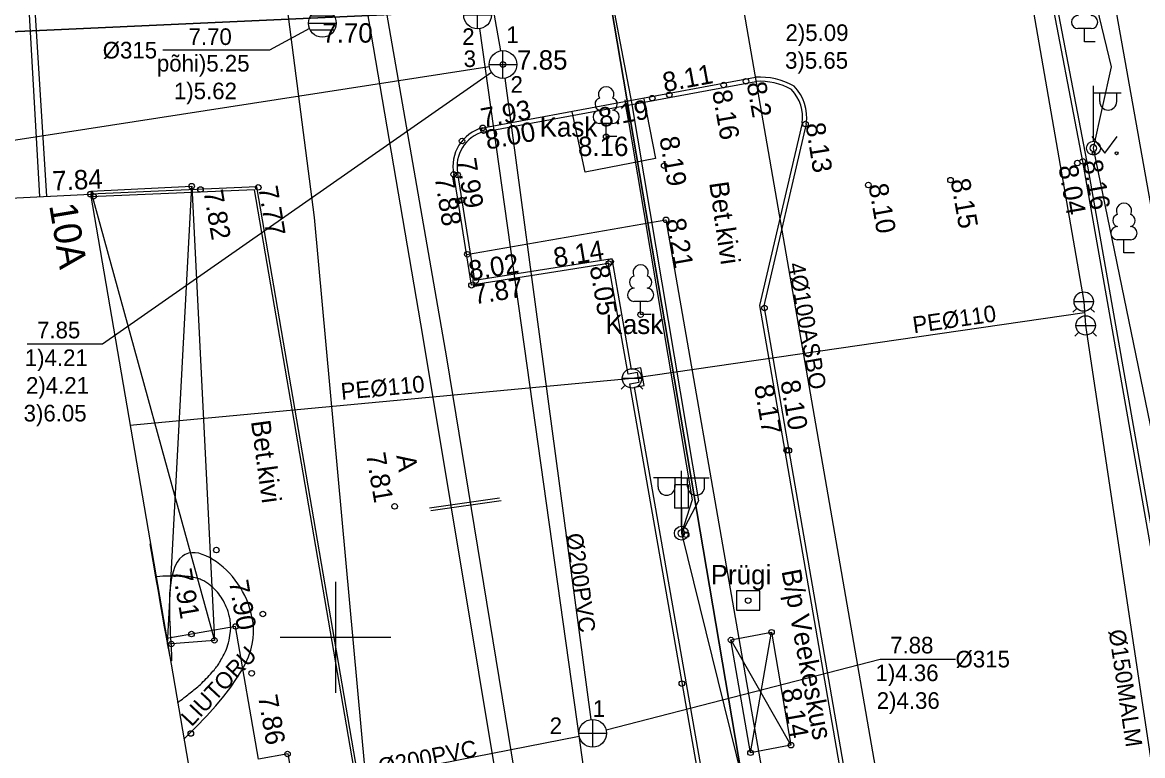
# Model space of a CAD drawing. Extents: x 473307 to 473719, y 6532843 to 6533381.
# Drawn here: x 473588.69 to 473629.14, y 6533195.73 to 6533222.19 of the extents above; entities that cross this region are included whole.
import ezdxf

# ---------------------------------------------------------------- set-up
doc = ezdxf.new("R2010")
doc.units = 0
for name, color, linetype in [('Default', 7, 'Continuous'), ('HALJASTUS', 7, 'Continuous'), ('HOONE', 7, 'Continuous'), ('HOONEDET', 7, 'Continuous'), ('KKAEV', 7, 'Continuous'), ('KKAEV_NR', 7, 'Continuous'), ('KORGUS', 7, 'Continuous'), ('KPKAABEL', 7, 'Continuous'), ('KTRASS', 7, 'Continuous'), ('KTRASS_TEKST', 7, 'Continuous'), ('LIIKLUS', 7, 'Continuous'), ('MPKAABEL', 7, 'Continuous'), ('PIIR', 7, 'Continuous'), ('POST', 7, 'Continuous'), ('PUU', 7, 'Continuous'), ('RAJATIS', 7, 'Continuous'), ('RAJATISEDET', 7, 'Continuous'), ('SITRASS', 7, 'Continuous'), ('SITRASS_TEKST', 7, 'Continuous'), ('SKKAEV', 7, 'Continuous'), ('SKKAEV_NR', 7, 'Continuous'), ('SKTRASS', 7, 'Continuous'), ('TEE', 7, 'Continuous'), ('TTRASS', 7, 'Continuous'), ('VKAEV', 7, 'Continuous'), ('VORK', 7, 'Continuous'), ('VTRASS', 7, 'Continuous'), ('VTRASS_TEKST', 7, 'Continuous')]:
    doc.layers.add(name, color=color, linetype=linetype)

# ---------------------------------------------------------------- blocks, each defined once
blk = doc.blocks.new('LEHTP1')
at = {"layer": 'Default'}
for p, q in [((0.48, 0.95), (-0.48, 0.95)), ((0, 0), (0, 0.95)), ((0.76, 0), (0, 0))]:
    blk.add_line(p, q, dxfattribs=at)
for centre, radius, start, end in [((0, 3.04), 0.554, 332.5799, 207.4201), ((-0.34, 2.345), 0.465, 109.02174, 253.14154), ((0.34, 2.345), 0.465, 286.85082, 70.98591), ((-0.475, 1.425), 0.475, 90.0016, 269.3953), ((0.475, 1.425), 0.475, 270.6047, 89.9984)]:
    blk.add_arc(centre, radius, start, end, dxfattribs=at)
blk = doc.blocks.new('KAKAEV')
at = {"layer": 'Default'}
for p, q in [((0, -1), (0, 1)), ((-1, 0), (1, 0))]:
    blk.add_line(p, q, dxfattribs=at)
blk.add_circle((0, 0), 1, dxfattribs=at)
blk = doc.blocks.new('REKAEV')
at = {"layer": 'Default'}
for p, q in [((-1, 0), (1, 0)), ((0.86, 0.5), (-0.86, 0.5)), ((0.86, -0.5), (-0.86, -0.5))]:
    blk.add_line(p, q, dxfattribs=at)
blk.add_circle((0, 0), 1, dxfattribs=at)
blk = doc.blocks.new('VESIIB')
at = {"layer": 'Default'}
for p, q in [((-0.7, 0), (0.7, 0)), ((-0.495, -0.495), (-0.774, -0.774)), ((0.495, -0.495), (0.774, -0.774))]:
    blk.add_line(p, q, dxfattribs=at)
blk.add_circle((0, 0), 0.7, dxfattribs=at)
blk = doc.blocks.new('MEPOST')
at = {"layer": 'Default'}
blk.add_circle((0, 0), 0.5, dxfattribs=at)
for start, end in [(0, 180), (180, 0)]:
    blk.add_arc((0, 0), 0.25, start, end, dxfattribs=at)
blk = doc.blocks.new('VAPOS2')
at = {"layer": 'Default'}
for p, q in [((0, 0.5), (0, 4.5)), ((0, 4), (-2, 4)), ((-1.679, 3.358), (-1.679, 4)), ((-0.453, 3.358), (-0.453, 4)), ((0, 4), (2, 4)), ((0.453, 3.358), (0.453, 4)), ((1.679, 3.358), (1.679, 4))]:
    blk.add_line(p, q, dxfattribs=at)
for centre in [(-1.066, 3.358), (1.066, 3.358)]:
    blk.add_arc(centre, 0.613, 180, 0, dxfattribs=at)
blk = doc.blocks.new('MURU')
at = {"layer": 'Default'}
for p, q in [((-0.927, 1.213), (0, 0)), ((0, 0), (0.891, 1.213))]:
    blk.add_line(p, q, dxfattribs=at)
for centre in [(-0.802, 0), (0.856, 0)]:
    blk.add_circle(centre, 0.11, dxfattribs=at)
blk = doc.blocks.new('VAPOST')
at = {"layer": 'Default'}
for p, q in [((0, 0.5), (0, 4.5)), ((0, 4), (2, 4)), ((0.453, 3.358), (0.453, 4)), ((1.679, 3.358), (1.679, 4))]:
    blk.add_line(p, q, dxfattribs=at)
blk.add_arc((1.066, 3.358), 0.613, 180, 0, dxfattribs=at)
blk = doc.blocks.new('LIIKLM')
at = {"layer": 'Default'}
for points in [[(-0.5, 3.5), (-0.5, 1.8)], [(0.5, 3.5), (-0.5, 3.5)], [(0.5, 3.5), (0.5, 1.8)], [(0.5, 1.8), (-0.5, 1.8)], [(0, 1.8), (0, 0)], [(0.5, 0), (0, 0)]]:
    blk.add_lwpolyline(points, dxfattribs=at)
blk = doc.blocks.new('VKORIS')
at = {"layer": 'Default'}
for p, q in [((0, 4), (0, -4)), ((-4, 0), (4, 0))]:
    blk.add_line(p, q, dxfattribs=at)
blk = doc.blocks.new('rajatm')
at = {"layer": 'Default'}
blk.add_lwpolyline([(0.843, 0.702), (-0.843, 0.702), (-0.843, -0.702), (0.843, -0.702)], close=True, dxfattribs=at)

msp = doc.modelspace()

# ---------------------------------------------------------------- linework, layer by layer
at = {"layer": 'HOONE'}
msp.add_lwpolyline([(473567.695, 6533214.825), (473591.147, 6533215.988), (473597.944, 6533176.46), (473598.021, 6533176.467), (473599.163, 6533169.838), (473569.973, 6533168.376), (473567.695, 6533214.825)], dxfattribs=at)
at = {"layer": 'HOONEDET'}
for p, q in [((473591.16, 6533216.1), (473595.626, 6533199.888)), ((473593.933, 6533199.746), (473594.814, 6533216.278))]:
    msp.add_line(p, q, dxfattribs=at)
msp.add_lwpolyline([(473591.16, 6533216.1), (473594.814, 6533216.278), (473595.626, 6533199.888), (473593.933, 6533199.746)], dxfattribs=at)
at = {"layer": 'KKAEV_NR'}
for points in [[(473605.633, 6533220.382), (473591.582, 6533210.582), (473588.861, 6533210.582)], [(473609.769, 6533196.66), (473619.666, 6533199.211), (473622.387, 6533199.211)]]:
    msp.add_lwpolyline(points, dxfattribs=at)
at = {"layer": 'KORGUS'}
for centre in [(473606.043, 6533220.668), (473614.016, 6533219.929), (473614.819, 6533220.064), (473612.051, 6533219.573), (473611.435, 6533219.453), (473605.315, 6533218.384), (473616.967, 6533218.52), (473604.567, 6533217.909), (473605.347, 6533218.284), (473609.771, 6533218.065), (473626.786, 6533217.111), (473626.98, 6533217.172), (473604.267, 6533216.706), (473604.409, 6533216.685), (473611.865, 6533217.019), (473594.804, 6533216.277), (473619.239, 6533216.318), (473622.205, 6533216.497), (473591.147, 6533215.988), (473591.262, 6533215.91), (473595.124, 6533216.16), (473597.208, 6533216.233), (473604.438, 6533215.747), (473604.56, 6533215.775), (473611.931, 6533215.063), (473604.758, 6533213.821), (473609.86, 6533213.484), (473609.933, 6533213.555), (473604.907, 6533212.703), (473605.063, 6533212.869), (473615.489, 6533211.883), (473611.016, 6533211.643), (473616.289, 6533206.748), (473616.365, 6533206.742), (473602.132, 6533204.723), (473612.658, 6533203.699), (473595.696, 6533203.145), (473614.897, 6533201.323), (473597.373, 6533200.84), (473594.8, 6533200.115), (473596.392, 6533200.39), (473615.743, 6533200.181), (473594.071, 6533199.757), (473595.626, 6533199.888), (473614.278, 6533199.901), (473596.971, 6533198.7), (473612.505, 6533198.328), (473594.776, 6533196.526), (473616.443, 6533196.104), (473598.267, 6533195.788), (473614.982, 6533195.832)]:
    msp.add_circle(centre, 0.1, dxfattribs=at)
at = {"layer": 'KPKAABEL'}
msp.add_lwpolyline([(473603.611, 6533167.485), (473599.245, 6533215.151), (473598.214, 6533223.062)], dxfattribs=at)
at = {"layer": 'KTRASS'}
for points in [[(473596.379, 6533274.552), (473599.595, 6533256.427), (473604.261, 6533230.713), (473605.956, 6533221.161)], [(473577.339, 6533216.231), (473605.549, 6533220.592)], [(473606.109, 6533220.173), (473609.219, 6533197.031)], [(473594.926, 6533193.714), (473608.797, 6533196.428)]]:
    msp.add_lwpolyline(points, dxfattribs=at)
at = {"layer": 'MPKAABEL'}
for points in [[(473636.059, 6533169.782), (473634.239, 6533181.673), (473632.606, 6533189.833), (473631.267, 6533197.327), (473629.932, 6533205.197), (473627.365, 6533217.651), (473628.02, 6533220.588), (473626.187, 6533228.162), (473625.63, 6533235.006), (473624.395, 6533236.238), (473625.088, 6533237.039), (473624.62, 6533240.685), (473623.001, 6533248.826), (473621.554, 6533256.337), (473620.191, 6533259.447), (473620.669, 6533261.927), (473620.008, 6533272.193), (473619.024, 6533281.587), (473618.831, 6533288.933), (473618.813, 6533289.306)], [(473627.365, 6533217.651), (473628.02, 6533220.588), (473626.187, 6533228.162), (473625.63, 6533235.006), (473624.395, 6533236.238)], [(473607.954, 6533230.431), (473608.769, 6533229.316), (473610.682, 6533219.295), (473613.1, 6533204.928), (473612.486, 6533203.753)], [(473608.769, 6533229.316), (473610.682, 6533219.295), (473613.1, 6533204.928), (473612.486, 6533203.753), (473615.782, 6533190.445), (473617.366, 6533178.496)], [(473610.448, 6533219.399), (473610.475, 6533219.258), (473612.881, 6533204.963), (473612.486, 6533203.753)], [(473634.239, 6533181.673), (473632.606, 6533189.833), (473631.267, 6533197.327), (473629.932, 6533205.197), (473627.365, 6533217.651)], [(473603.39, 6533204.676), (473605.925, 6533205.032)], [(473603.44, 6533204.573), (473605.975, 6533204.929)], [(473612.486, 6533203.753), (473615.782, 6533190.445), (473617.366, 6533178.496), (473617.205, 6533177.267)]]:
    msp.add_lwpolyline(points, dxfattribs=at)
at = {"layer": 'PIIR'}
msp.add_lwpolyline([(473678.608, 6532842.593), (473677.66, 6532847.73), (473668.24, 6532906.4), (473664.64, 6532927.81), (473654.16, 6532926.37), (473630.89, 6533065.72), (473641.36, 6533067.51), (473636.3, 6533097.55), (473618.8, 6533170.64), (473609.94, 6533222.84), (473601.54, 6533272.81), (473599.09, 6533295.91), (473592.3, 6533328.43), (473587.14, 6533353.72), (473584.47, 6533353.28), (473580.56, 6533374.06), (473585.23, 6533374.14), (473584.699, 6533380.885)], dxfattribs=at)
for points in [[(473586.5, 6533271.93), (473601.56, 6533272.81), (473609.94, 6533222.84), (473586.39, 6533221.76), (473567.96, 6533221.17), (473565.61, 6533263.9), (473587.68, 6533264.9)], [(473558.63, 6533220.73), (473567.96, 6533221.17), (473586.39, 6533221.76), (473609.94, 6533222.84), (473618.8, 6533170.64), (473601.75, 6533167.04), (473561.43, 6533165.2), (473559.2, 6533209.37)]]:
    msp.add_lwpolyline(points, close=True, dxfattribs=at)
at = {"layer": 'RAJATIS'}
msp.add_lwpolyline([(473614.278, 6533199.901), (473615.743, 6533200.181), (473616.443, 6533196.104), (473614.982, 6533195.832), (473614.278, 6533199.901)], dxfattribs=at)
for points in [[(473594.523, 6533196.32), (473596.971, 6533198.7), (473597.373, 6533200.84), (473595.696, 6533203.145), (473593.308, 6533203.375), (473594.523, 6533196.32), (473593.308, 6533203.375)], [(473594.295, 6533197.641), (473594.359, 6533197.689), (473594.418, 6533197.733), (473594.807, 6533198.026), (473595.146, 6533198.31), (473595.626, 6533198.82), (473595.793, 6533199.044), (473596.048, 6533199.517), (473596.14, 6533199.778), (473596.209, 6533200.188), (473596.217, 6533200.34), (473596.2, 6533200.602), (473596.181, 6533200.712), (473596.118, 6533200.944), (473596.073, 6533201.062), (473595.906, 6533201.406), (473595.749, 6533201.62), (473595.495, 6533201.863), (473595.408, 6533201.931), (473595.225, 6533202.046), (473595.137, 6533202.086), (473594.915, 6533202.154), (473594.783, 6533202.179), (473594.476, 6533202.21), (473594.3, 6533202.215), (473593.923, 6533202.209), (473593.724, 6533202.198), (473593.512, 6533202.185)]]:
    msp.add_open_spline(points, degree=3, dxfattribs=at)
at = {"layer": 'RAJATISEDET'}
for points in [[(473614.278, 6533199.901), (473616.443, 6533196.104)], [(473614.982, 6533195.832), (473615.743, 6533200.181)]]:
    msp.add_lwpolyline(points, dxfattribs=at)
at = {"layer": 'SITRASS'}
msp.add_lwpolyline([(473619.598, 6533194.755), (473606.651, 6533269.171)], dxfattribs=at)
at = {"layer": 'SKKAEV_NR'}
msp.add_lwpolyline([(473599.056, 6533221.966), (473597.62, 6533221.186), (473593.765, 6533221.186)], dxfattribs=at)
at = {"layer": 'SKTRASS'}
msp.add_line((473605.197, 6533221.962), (473611.461, 6533177.365), dxfattribs=at)
at = {"layer": 'TEE'}
for points in [[(473633.632, 6533192.148), (473626.508, 6533232.017), (473625.67, 6533237.189), (473623.189, 6533236.957)], [(473631.487, 6533191.503), (473631.245, 6533193.006), (473626.98, 6533217.172), (473623.189, 6533236.957)], [(473631.635, 6533191.527), (473631.393, 6533193.031), (473627.128, 6533217.199), (473623.336, 6533236.985)], [(473605.315, 6533218.384), (473615.163, 6533220.21)], [(473605.348, 6533218.238), (473615.181, 6533220.061)], [(473611.137, 6533219.428), (473611.553, 6533217.274), (473609.014, 6533216.78), (473608.54, 6533218.956)], [(473616.846, 6533218.552), (473615.311, 6533211.969), (473616.217, 6533206.716), (473618.71, 6533192.337), (473619.951, 6533185.079), (473623.699, 6533179.197)], [(473616.994, 6533218.524), (473615.464, 6533211.964), (473616.365, 6533206.742), (473618.858, 6533192.362), (473620.094, 6533185.134), (473623.834, 6533179.264)], [(473610.621, 6533209.151), (473610.966, 6533209.211), (473610.906, 6533209.55), (473610.562, 6533209.489), (473609.86, 6533213.484), (473604.907, 6533212.703), (473604.267, 6533216.706)], [(473610.795, 6533209.029), (473611.14, 6533209.089), (473611.028, 6533209.723), (473610.683, 6533209.663), (473609.982, 6533213.655), (473605.032, 6533212.874), (473604.415, 6533216.733)], [(473600.715, 6533167.193), (473596.954, 6533189.064), (473601.687, 6533189.906), (473597.156, 6533216.255), (473591.147, 6533215.988)], [(473600.616, 6533167.176), (473596.838, 6533189.145), (473601.572, 6533189.987), (473597.073, 6533216.151), (473591.151, 6533215.888)], [(473604.729, 6533213.816), (473611.931, 6533215.063), (473614.566, 6533199.957), (473614.566, 6533199.957), (473615.517, 6533194.507), (473615.909, 6533192.334), (473618.695, 6533176.327)], [(473622.771, 6533177.029), (473616.417, 6533175.935), (473613.178, 6533194.593), (473610.621, 6533209.151)], [(473622.737, 6533177.176), (473616.539, 6533176.108), (473613.326, 6533194.619), (473610.795, 6533209.029)], [(473599.377, 6533189.495), (473598.294, 6533195.792), (473597.214, 6533195.606), (473596.392, 6533200.39), (473593.903, 6533199.96)]]:
    msp.add_lwpolyline(points, dxfattribs=at)
for centre, radius, start, end in [((473615.308, 6533217.701), 2.513, 60.2748, 93.297), ((473615.308, 6533217.701), 2.363, 60.7832, 93.0715), ((473615.416, 6533218.765), 1.446, 351.5554, 43.6997), ((473615.416, 6533218.765), 1.596, 351.3297, 44.5155), ((473605.673, 6533216.994), 1.436, 104.446, 191.5793), ((473605.673, 6533216.994), 1.286, 104.6697, 191.7208)]:
    msp.add_arc(centre, radius, start, end, dxfattribs=at)
at = {"layer": 'TTRASS'}
for points in [[(473592.297, 6533277.757), (473596.188, 6533254.087), (473601.84, 6533222.521), (473604, 6533210.082), (473607.02, 6533191.72), (473607.264, 6533190.194), (473603.552, 6533189.561), (473604.136, 6533186.261), (473607.868, 6533186.888), (473612.623, 6533162.34), (473616.873, 6533138.735), (473619.773, 6533121.514), (473620.151, 6533119.324)], [(473591.775, 6533277.426), (473595.59, 6533253.766), (473601.028, 6533223.219), (473603.147, 6533210.812), (473606.172, 6533192.662), (473606.51, 6533190.705), (473602.77, 6533190.028), (473603.588, 6533185.543), (473607.3, 6533186.208), (473612.067, 6533161.644), (473616.282, 6533137.983), (473619.426, 6533120.252), (473619.546, 6533119.497)], [(473589.32, 6533215.907), (473588.935, 6533222.692)], [(473589.576, 6533215.918), (473589.166, 6533222.448)]]:
    msp.add_lwpolyline(points, dxfattribs=at)
at = {"layer": 'VTRASS'}
for points in [[(473610.467, 6533298.54), (473612.816, 6533284.928), (473621.946, 6533241.242), (473627.014, 6533212.114), (473627.084, 6533211.254), (473634.761, 6533160.18), (473647.035, 6533084.422), (473650.297, 6533065.838)], [(473592.57, 6533207.655), (473610.704, 6533209.344), (473627.041, 6533211.717)]]:
    msp.add_lwpolyline(points, dxfattribs=at)

# ---------------------------------------------------------------- block references
at = {"layer": 'HALJASTUS', "xscale": 0.5, "yscale": 0.5}
msp.add_blockref('MURU', (473627.771, 6533217.467), dxfattribs=at)
at = {"layer": 'KKAEV', "xscale": 0.5, "yscale": 0.5}
for p in [(473606.043, 6533220.668), (473609.285, 6533196.536)]:
    msp.add_blockref('KAKAEV', p, dxfattribs=at)
at = {"layer": 'LIIKLUS', "xscale": 0.5, "yscale": 0.5}
msp.add_blockref('LIIKLM', (473612.486, 6533203.753), dxfattribs=at)
at = {"layer": 'POST', "xscale": 0.5, "yscale": 0.5}
for name, p in [('VAPOST', (473627.365, 6533217.651)), ('MEPOST', (473627.365, 6533217.651)), ('VAPOS2', (473612.486, 6533203.753)), ('MEPOST', (473612.486, 6533203.753))]:
    msp.add_blockref(name, p, dxfattribs=at)
at = {"layer": 'PUU', "xscale": 0.5, "yscale": 0.5}
for p in [(473627.047, 6533221.487), (473609.771, 6533218.065), (473628.467, 6533213.868), (473611.016, 6533211.643)]:
    msp.add_blockref('LEHTP1', p, dxfattribs=at)
at = {"layer": 'RAJATIS', "xscale": 0.5, "yscale": 0.5}
msp.add_blockref('rajatm', (473614.897, 6533201.323), dxfattribs=at)
at = {"layer": 'SKKAEV', "xscale": 0.5, "yscale": 0.5}
for name, p in [('KAKAEV', (473605.127, 6533222.457)), ('REKAEV', (473599.522, 6533222.157))]:
    msp.add_blockref(name, p, dxfattribs=at)
at = {"layer": 'VKAEV', "xscale": 0.5, "yscale": 0.5}
for p in [(473627.014, 6533212.114), (473627.084, 6533211.254), (473610.704, 6533209.344)]:
    msp.add_blockref('VESIIB', p, dxfattribs=at)
at = {"layer": 'VORK', "xscale": 0.5, "yscale": 0.5}
msp.add_blockref('VKORIS', (473600, 6533200), dxfattribs=at)

# ---------------------------------------------------------------- texts
at = {"layer": 'HOONE'}
msp.add_text('10A', height=1, rotation=279.457, dxfattribs=at).set_placement((473589.657, 6533215.591))
at = {"layer": 'KKAEV_NR'}
for s, p in [('1', (473606.167, 6533221.445)), ('3', (473604.625, 6533220.577)), ('2', (473606.318, 6533219.648)), ('7.85', (473589.222, 6533210.787)), ('1)4.21', (473588.779, 6533209.787)), ('2)4.21', (473588.822, 6533208.787)), ('3)6.05', (473588.736, 6533207.787)), ('7.88', (473620.026, 6533199.416)), ('%%c315', (473622.387, 6533198.911)), ('1)4.36', (473619.498, 6533198.416)), ('2)4.36', (473619.54, 6533197.416)), ('1', (473609.288, 6533197.128)), ('2', (473607.73, 6533196.506))]:
    msp.add_text(s, height=0.6, dxfattribs=at).set_placement(p)
at = {"layer": 'KORGUS'}
for s, p in [('7.70', (473599.522, 6533221.457)), ('7.85', (473606.553, 6533220.484)), ('8.16', (473608.754, 6533217.365))]:
    msp.add_text(s, height=0.7, dxfattribs=at).set_placement(p)
for s, rotation, p in [('8.11', 10.5038, (473611.879, 6533219.672)), ('8.2', 279.9052, (473614.843, 6533219.991)), ('8.16', 279.9052, (473613.595, 6533219.698)), ('7.93', 10.5038, (473605.315, 6533218.384)), ('8.19', 10.5038, (473609.563, 6533218.394)), ('8.00', 10.5038, (473605.475, 6533217.595)), ('8.13', 279.0803, (473616.967, 6533218.52)), ('8.19', 279.9052, (473611.69, 6533218.02)), ('7.99', 279.0856, (473604.376, 6533217.235)), ('8.16', 280, (473626.98, 6533217.172)), ('7.84', 2.5441, (473589.785, 6533216.117)), ('8.04', 280, (473626.097, 6533216.989)), ('7.88', 279.0856, (473603.576, 6533216.595)), ('8.15', 280, (473622.205, 6533216.497)), ('7.82', 279.7568, (473595.229, 6533216.091)), ('7.77', 279.5847, (473597.208, 6533216.233)), ('8.10', 280, (473619.239, 6533216.318)), ('8.21', 279.9052, (473611.931, 6533215.063)), ('8.14', 9.4678, (473607.93, 6533213.347)), ('8.02', 8.9586, (473604.861, 6533212.878)), ('8.05', 279.9623, (473609.171, 6533213.362)), ('7.87', 8.9586, (473605.016, 6533212.011)), ('8.17', 279.8357, (473615.112, 6533209.066)), ('8.10', 279.8357, (473616.06, 6533209.225)), ('7.81', 279.7568, (473601.097, 6533206.609)), ('7.91', 279.7568, (473594.103, 6533202.42)), ('7.90', 279.7568, (473596.148, 6533202.01)), ('7.86', 279.7568, (473597.199, 6533197.87)), ('8.14', 279.7452, (473616.099, 6533198.108))]:
    msp.add_text(s, height=0.7, rotation=rotation, dxfattribs=at).set_placement(p)
at = {"layer": 'KTRASS_TEKST'}
for rotation, p in [(277.6519, (473608.32, 6533203.717)), (11.0716, (473601.605, 6533195.021))]:
    msp.add_text('%%c200PVC', height=0.6, rotation=rotation, dxfattribs=at).set_placement(p)
at = {"layer": 'LIIKLUS'}
msp.add_text('B/p Veekeskus', height=0.7, rotation=280.6344, dxfattribs=at).set_placement((473616.1, 6533202.391))
at = {"layer": 'PUU'}
for p in [(473607.371, 6533218.065), (473609.749, 6533210.943)]:
    msp.add_text('Kask', height=0.7, dxfattribs=at).set_placement(p)
at = {"layer": 'RAJATIS'}
msp.add_text('Prügi', height=0.7, dxfattribs=at).set_placement((473613.547, 6533201.908))
msp.add_text('LIUTORU', height=0.6, rotation=47.0258, dxfattribs=at).set_placement((473594.802, 6533196.745))
at = {"layer": 'SITRASS_TEKST'}
msp.add_text('4%%c100ASBO', height=0.6, rotation=279.8694, dxfattribs=at).set_placement((473616.342, 6533213.47))
at = {"layer": 'SKKAEV_NR'}
for s, p in [('2)5.09', (473616.246, 6533221.517)), ('7.70', (473594.692, 6533221.373)), ('2', (473604.574, 6533221.374)), ('%%c315', (473591.593, 6533220.886)), ('põhi)5.25', (473593.549, 6533220.414)), ('3)5.65', (473616.232, 6533220.517)), ('1)5.62', (473594.164, 6533219.414))]:
    msp.add_text(s, height=0.6, dxfattribs=at).set_placement(p)
at = {"layer": 'TEE'}
for s, rotation, p in [('Bet.kivi', 278.2308, (473613.489, 6533216.397)), ('Bet.kivi', 277.791, (473596.943, 6533207.791)), ('A', 278.4592, (473602.193, 6533206.555))]:
    msp.add_text(s, height=0.7, rotation=rotation, dxfattribs=at).set_placement(p)
at = {"layer": 'VTRASS_TEKST'}
for s, rotation, p in [('PE%%c110', 8.2628, (473620.883, 6533210.965)), ('PE%%c110', 5.3218, (473600.218, 6533208.568)), ('%%c150MALM', 278.5487, (473627.91, 6533200.239))]:
    msp.add_text(s, height=0.6, rotation=rotation, dxfattribs=at).set_placement(p)

doc.saveas('drawing.dxf')
